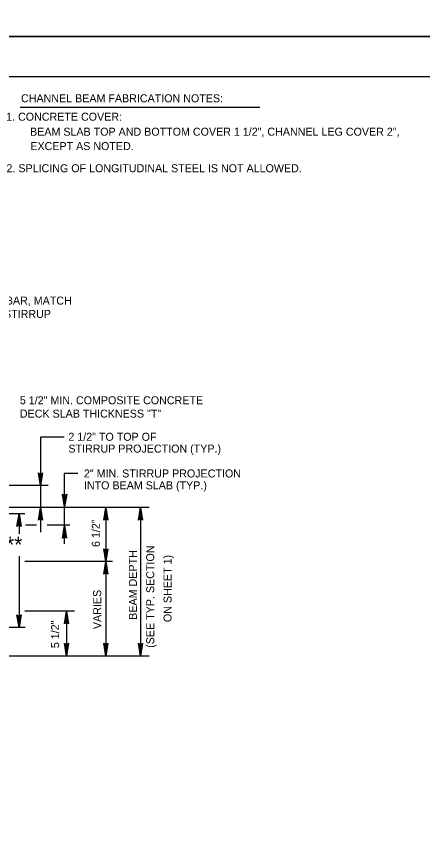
# Model space of a CAD drawing. Extents: x 642009 to 642864, y 298232 to 300014.
# Drawn here: x 642285.5 to 642437.9, y 298526.3 to 298833.3 of the extents above; entities that cross this region are included whole.
import ezdxf

# ---------------------------------------------------------------- set-up
doc = ezdxf.new("R2010")
doc.units = 0
for name, color, linetype in [('1', 7, 'Continuous'), ('2', 7, 'Continuous'), ('22', 7, 'Continuous'), ('PLT-BNDY', 7, 'Continuous')]:
    doc.layers.add(name, color=color, linetype=linetype)

msp = doc.modelspace()

# ---------------------------------------------------------------- linework, layer by layer
at = {"layer": '1'}
for points in [[(642295.08, 298662.04), (642294.75, 298661.87), (642294.51, 298657.5), (642295.08, 298662.04), (642295.28, 298662.27), (642294.51, 298657.5), (642294.3, 298661.87), (642293.97, 298662.03), (642294.51, 298657.5), (642293.75, 298662.27), (642293.97, 298662.03)], [(642304.14, 298654.07), (642303.81, 298653.9), (642303.57, 298649.53), (642304.14, 298654.07), (642304.34, 298654.3), (642303.57, 298649.53), (642303.36, 298653.9), (642303.03, 298654.06), (642303.57, 298649.53), (642302.81, 298654.3), (642303.03, 298654.06)], [(642293.94, 298644.77), (642294.27, 298644.94), (642294.51, 298649.31), (642293.94, 298644.77), (642293.74, 298644.54), (642294.51, 298649.31), (642294.73, 298644.94), (642295.05, 298644.79), (642294.51, 298649.31), (642295.27, 298644.54), (642295.05, 298644.79)], [(642318.5, 298644.77), (642318.82, 298644.94), (642319.07, 298649.31), (642318.5, 298644.77), (642318.3, 298644.54), (642319.07, 298649.31), (642319.28, 298644.94), (642319.61, 298644.79), (642319.07, 298649.31), (642319.82, 298644.54), (642319.61, 298644.79)], [(642331.48, 298644.77), (642331.81, 298644.94), (642332.05, 298649.31), (642331.48, 298644.77), (642331.28, 298644.54), (642332.05, 298649.31), (642332.26, 298644.94), (642332.59, 298644.79), (642332.05, 298649.31), (642332.81, 298644.54), (642332.59, 298644.79)], [(642285.88, 298642.37), (642286.21, 298642.54), (642286.45, 298646.91), (642285.88, 298642.37), (642285.68, 298642.13), (642286.45, 298646.91), (642286.67, 298642.54), (642286.99, 298642.38), (642286.45, 298646.91), (642287.21, 298642.13), (642286.99, 298642.38)], [(642302.95, 298637.99), (642303.28, 298638.16), (642303.52, 298642.53), (642302.95, 298637.99), (642302.75, 298637.76), (642303.52, 298642.53), (642303.73, 298638.17), (642304.06, 298638.01), (642303.52, 298642.53), (642304.28, 298637.76), (642304.06, 298638.01)], [(642319.64, 298633.6), (642319.31, 298633.43), (642319.07, 298629.06), (642319.64, 298633.6), (642319.83, 298633.84), (642319.07, 298629.06), (642318.85, 298633.43), (642318.52, 298633.59), (642319.07, 298629.06), (642318.31, 298633.84), (642318.52, 298633.59)], [(642318.5, 298624.52), (642318.82, 298624.69), (642319.07, 298629.06), (642318.5, 298624.52), (642318.3, 298624.29), (642319.07, 298629.06), (642319.28, 298624.69), (642319.61, 298624.54), (642319.07, 298629.06), (642319.82, 298624.29), (642319.61, 298624.54)], [(642287.02, 298608.85), (642286.69, 298608.68), (642286.45, 298604.31), (642287.02, 298608.85), (642287.22, 298609.09), (642286.45, 298604.31), (642286.23, 298608.68), (642285.91, 298608.84), (642286.45, 298604.31), (642285.69, 298609.09), (642285.91, 298608.84)], [(642303.66, 298605.96), (642303.99, 298606.13), (642304.23, 298610.5), (642303.66, 298605.96), (642303.46, 298605.73), (642304.23, 298610.5), (642304.44, 298606.13), (642304.77, 298605.97), (642304.23, 298610.5), (642304.99, 298605.73), (642304.77, 298605.97)], [(642304.8, 298598.17), (642304.47, 298598), (642304.23, 298593.63), (642304.8, 298598.17), (642305, 298598.4), (642304.23, 298593.63), (642304.01, 298597.99), (642303.69, 298598.15), (642304.23, 298593.63), (642303.47, 298598.4), (642303.69, 298598.15)], [(642319.64, 298598.17), (642319.31, 298598), (642319.07, 298593.63), (642319.64, 298598.17), (642319.83, 298598.4), (642319.07, 298593.63), (642318.85, 298597.99), (642318.52, 298598.15), (642319.07, 298593.63), (642318.31, 298598.4), (642318.52, 298598.15)], [(642332.62, 298598.17), (642332.29, 298598), (642332.05, 298593.63), (642332.62, 298598.17), (642332.82, 298598.4), (642332.05, 298593.63), (642331.83, 298597.99), (642331.51, 298598.15), (642332.05, 298593.63), (642331.29, 298598.4), (642331.51, 298598.15)]]:
    msp.add_lwpolyline(points, dxfattribs=at)
at = {"layer": '2'}
for p, q in [((642048.66, 298810.82), (642834.66, 298810.82)), ((642286.86, 298799.36), (642376.74, 298799.36)), ((642294.51, 298675.7), (642294.51, 298639.99)), ((642303.37, 298675.7), (642294.51, 298675.7)), ((642303.42, 298662.03), (642303.42, 298642.59)), ((642308.52, 298662.03), (642303.42, 298662.03)), ((642297.41, 298657.5), (642265.51, 298657.5)), ((642335.23, 298649.31), (642280.82, 298649.31)), ((642319.07, 298649.31), (642319.07, 298629.06)), ((642332.05, 298649.31), (642332.05, 298593.63)), ((642288.58, 298646.91), (642268.61, 298646.91)), ((642286.45, 298646.91), (642286.45, 298639.4)), ((642292.95, 298642.72), (642288.84, 298642.72)), ((642305.48, 298642.72), (642297.07, 298642.72)), ((642303.42, 298642.59), (642303.42, 298635.72)), ((642286.45, 298631.03), (642286.45, 298604.31)), ((642321.56, 298629.06), (642288.61, 298629.06)), ((642319.07, 298629.06), (642319.07, 298593.63)), ((642307.21, 298610.5), (642288.68, 298610.5)), ((642304.23, 298610.5), (642304.23, 298593.63)), ((642288.71, 298604.31), (642269.55, 298604.31)), ((642304.23, 298600.56), (642304.23, 298593.63)), ((642335.31, 298593.63), (642270.33, 298593.63)), ((642304.23, 298593.63), (642304.23, 298593.63))]:
    msp.add_line(p, q, dxfattribs=at)
at = {"layer": 'PLT-BNDY'}
for points in [[(642008.66, 299419.82), (642849.66, 299419.82), (642849.66, 298825.82), (642008.66, 298825.82)], [(642008.66, 298825.82), (642849.66, 298825.82), (642849.66, 298231.82), (642008.66, 298231.82)]]:
    msp.add_lwpolyline(points, close=True, dxfattribs=at)

# ---------------------------------------------------------------- texts
at = {"layer": '2'}
for s, height, p in [('CHANNEL BEAM FABRICATION NOTES:', 3, (642287.2, 298801.13)), ('1. CONCRETE COVER:', 3, (642281.62, 298794.23)), ('BEAM SLAB TOP AND BOTTOM COVER 1 1/2", CHANNEL LEG COVER 2",', 3, (642290.6, 298788.61)), ('EXCEPT AS NOTED.', 3, (642290.7, 298783.22)), ('2. SPLICING OF LONGITUDINAL STEEL IS NOT ALLOWED.', 3, (642281.75, 298774.91)), ('#4 BAR, MATCH', 3, (642275.92, 298725.32)), ('W/STIRRUP', 3, (642275.92, 298720.32)), ('5 1/2" MIN. COMPOSITE CONCRETE', 3, (642286.77, 298687.97)), ('DECK SLAB THICKNESS "T"', 3, (642286.77, 298682.97)), ('***', 5.88, (642278.53, 298632.43))]:
    msp.add_text(s, height=height, dxfattribs=at).set_placement(p)
for s, p in [('6 1/2"', (642316.76, 298634.49)), ('BEAM DEPTH', (642330.67, 298607.22)), ('(SEE TYP. SECTION', (642337.17, 298596.72)), ('ON SHEET 1)', (642343.67, 298606.35)), ('VARIES', (642317.27, 298603.73)), ('5 1/2"', (642301.5, 298596.58))]:
    msp.add_text(s, height=3, rotation=90, dxfattribs=at).set_placement(p)
at = {"layer": '22'}
for s, p in [('2 1/2" TO TOP OF', (642304.97, 298674.3)), ('STIRRUP PROJECTION (TYP.)', (642304.97, 298669.86)), ('2" MIN. STIRRUP PROJECTION', (642310.8, 298660.55)), ('INTO BEAM SLAB (TYP.)', (642310.8, 298656.11))]:
    msp.add_text(s, height=2.9997, rotation=360, dxfattribs=at).set_placement(p)

doc.saveas('drawing.dxf')
